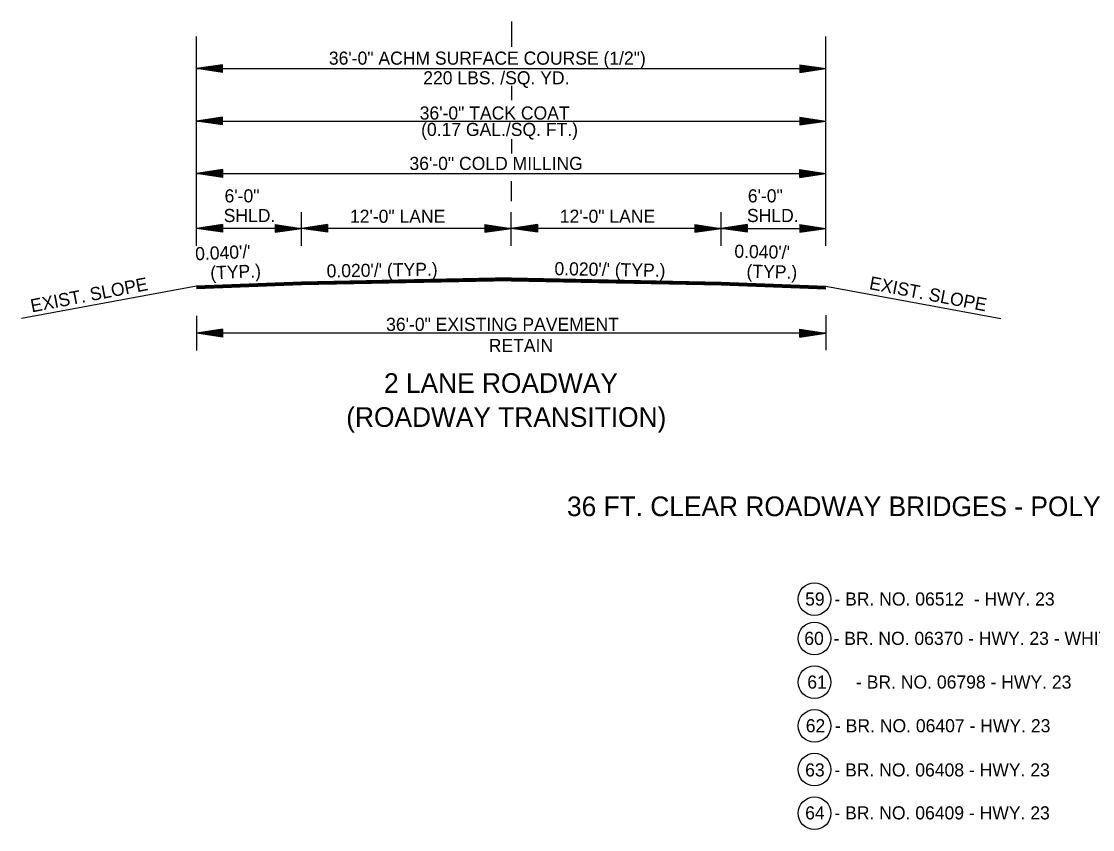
# Model space of a CAD drawing. Extents: x 550980 to 1930787, y -1972975 to 596640.
# Drawn here: x 551028 to 551641, y -1972925 to -1972463 of the extents above; entities that cross this region are included whole.
import ezdxf

# ---------------------------------------------------------------- set-up
doc = ezdxf.new("R2010")
doc.units = 0
doc.layers.add('R_Border', color=7, linetype='Continuous')
doc.layers.add('R_Draft', color=7, linetype='Continuous')

msp = doc.modelspace()

# ---------------------------------------------------------------- linework, layer by layer
at = {"layer": 'R_Border'}
for p, q in [((551308.3, -1972462.9), (551308.3, -1972477.4)), ((551143.09, -1972487.65), (551128.09, -1972489.9)), ((551128.09, -1972489.9), (551488.09, -1972489.9)), ((551143.09, -1972492.15), (551128.09, -1972489.9)), ((551143.09, -1972488.03), (551130.59, -1972489.9)), ((551143.09, -1972491.78), (551130.59, -1972489.9)), ((551143.09, -1972488.41), (551133.17, -1972489.9)), ((551143.09, -1972491.39), (551133.17, -1972489.9)), ((551143.09, -1972488.78), (551135.67, -1972489.9)), ((551143.09, -1972491.02), (551135.67, -1972489.9)), ((551143.09, -1972489.17), (551138.21, -1972489.9)), ((551143.09, -1972490.63), (551138.21, -1972489.9)), ((551143.09, -1972489.55), (551140.72, -1972489.9)), ((551143.09, -1972490.25), (551140.72, -1972489.9)), ((551143.09, -1972492.15), (551143.09, -1972487.65)), ((551473.09, -1972487.65), (551488.09, -1972489.9)), ((551473.09, -1972487.65), (551473.09, -1972492.15)), ((551473.09, -1972488.03), (551485.58, -1972489.9)), ((551473.09, -1972488.41), (551483, -1972489.9)), ((551473.09, -1972488.78), (551480.51, -1972489.9)), ((551473.09, -1972489.17), (551477.96, -1972489.9)), ((551473.09, -1972489.55), (551475.46, -1972489.9)), ((551473.09, -1972492.15), (551488.09, -1972489.9)), ((551473.09, -1972490.64), (551477.96, -1972489.9)), ((551473.09, -1972491.39), (551483, -1972489.9)), ((551473.09, -1972491.78), (551485.58, -1972489.9)), ((551473.09, -1972491.02), (551480.51, -1972489.9)), ((551473.09, -1972490.25), (551475.46, -1972489.9)), ((551308.3, -1972499.84), (551308.3, -1972508.04)), ((551143.09, -1972517.65), (551128.09, -1972519.9)), ((551128.09, -1972519.9), (551488.09, -1972519.9)), ((551143.09, -1972522.15), (551128.09, -1972519.9)), ((551143.09, -1972518.03), (551130.59, -1972519.9)), ((551143.09, -1972521.78), (551130.59, -1972519.9)), ((551143.09, -1972518.41), (551133.17, -1972519.9)), ((551143.09, -1972521.39), (551133.17, -1972519.9)), ((551143.09, -1972518.78), (551135.67, -1972519.9)), ((551143.09, -1972521.02), (551135.67, -1972519.9)), ((551143.09, -1972519.17), (551138.21, -1972519.9)), ((551143.09, -1972520.63), (551138.21, -1972519.9)), ((551143.09, -1972519.55), (551140.72, -1972519.9)), ((551143.09, -1972520.25), (551140.72, -1972519.9)), ((551143.09, -1972522.15), (551143.09, -1972517.65)), ((551473.09, -1972517.65), (551488.09, -1972519.9)), ((551473.09, -1972517.65), (551473.09, -1972522.15)), ((551473.09, -1972518.03), (551485.58, -1972519.9)), ((551473.09, -1972518.41), (551483, -1972519.9)), ((551473.09, -1972518.78), (551480.51, -1972519.9)), ((551473.09, -1972519.17), (551477.96, -1972519.9)), ((551473.09, -1972519.55), (551475.46, -1972519.9)), ((551473.09, -1972522.15), (551488.09, -1972519.9)), ((551473.09, -1972520.64), (551477.96, -1972519.9)), ((551473.09, -1972521.39), (551483, -1972519.9)), ((551473.09, -1972521.78), (551485.58, -1972519.9)), ((551473.09, -1972521.02), (551480.51, -1972519.9)), ((551473.09, -1972520.25), (551475.46, -1972519.9)), ((551308.3, -1972530.36), (551308.3, -1972538.56)), ((551128.09, -1972549.9), (551488.09, -1972549.9))]:
    msp.add_line(p, q, dxfattribs=at)
for centre in [(551481.56, -1972793.43), (551481.56, -1972815.96), (551481.56, -1972840.96), (551481.56, -1972865.96), (551481.56, -1972890.96), (551481.56, -1972915.96)]:
    msp.add_circle(centre, 9.34, dxfattribs=at)
at = {"layer": 'R_Draft'}
for p, q in [((551128.09, -1972591.31), (551128.09, -1972471.5)), ((551488.09, -1972591.31), (551488.09, -1972471.5)), ((551143.09, -1972547.65), (551128.09, -1972549.9)), ((551143.09, -1972552.15), (551128.09, -1972549.9)), ((551143.09, -1972548.03), (551130.59, -1972549.9)), ((551143.09, -1972551.78), (551130.59, -1972549.9)), ((551143.09, -1972548.41), (551133.17, -1972549.9)), ((551143.09, -1972551.39), (551133.17, -1972549.9)), ((551143.09, -1972548.78), (551135.67, -1972549.9)), ((551143.09, -1972551.02), (551135.67, -1972549.9)), ((551143.09, -1972549.17), (551138.21, -1972549.9)), ((551143.09, -1972550.64), (551138.21, -1972549.9)), ((551143.09, -1972549.55), (551140.72, -1972549.9)), ((551143.09, -1972550.25), (551140.72, -1972549.9)), ((551143.09, -1972547.65), (551143.09, -1972552.15)), ((551473.09, -1972547.65), (551488.09, -1972549.9)), ((551473.09, -1972552.15), (551473.09, -1972547.65)), ((551473.09, -1972548.03), (551485.58, -1972549.9)), ((551473.09, -1972548.41), (551483, -1972549.9)), ((551473.09, -1972548.78), (551480.51, -1972549.9)), ((551473.09, -1972549.17), (551477.96, -1972549.9)), ((551473.09, -1972549.55), (551475.46, -1972549.9)), ((551473.09, -1972552.15), (551488.09, -1972549.9)), ((551473.09, -1972550.63), (551477.96, -1972549.9)), ((551473.09, -1972551.39), (551483, -1972549.9)), ((551473.09, -1972551.78), (551485.58, -1972549.9)), ((551473.09, -1972551.02), (551480.51, -1972549.9)), ((551473.09, -1972550.25), (551475.46, -1972549.9)), ((551308.3, -1972565.67), (551308.3, -1972554.22)), ((551188.09, -1972591.31), (551188.09, -1972572.12)), ((551308.09, -1972591.31), (551308.09, -1972572.12)), ((551428.09, -1972591.31), (551428.09, -1972572.12)), ((551143.09, -1972579.06), (551128.09, -1972581.31)), ((551188.09, -1972581.31), (551128.09, -1972581.31)), ((551143.09, -1972583.56), (551128.09, -1972581.31)), ((551143.09, -1972579.43), (551130.59, -1972581.31)), ((551143.09, -1972583.18), (551130.59, -1972581.31)), ((551143.09, -1972579.82), (551133.17, -1972581.31)), ((551143.09, -1972582.8), (551133.17, -1972581.31)), ((551143.09, -1972580.19), (551135.67, -1972581.31)), ((551143.09, -1972582.43), (551135.67, -1972581.31)), ((551143.09, -1972580.58), (551138.21, -1972581.31)), ((551143.09, -1972582.04), (551138.21, -1972581.31)), ((551143.09, -1972580.96), (551140.72, -1972581.31)), ((551143.09, -1972581.66), (551140.72, -1972581.31)), ((551143.09, -1972579.06), (551143.09, -1972583.56)), ((551173.09, -1972579.06), (551188.09, -1972581.31)), ((551173.09, -1972579.06), (551173.09, -1972583.56)), ((551173.09, -1972579.43), (551185.58, -1972581.31)), ((551173.09, -1972579.82), (551183, -1972581.31)), ((551173.09, -1972580.19), (551180.51, -1972581.31)), ((551173.09, -1972580.58), (551177.96, -1972581.31)), ((551173.09, -1972580.96), (551175.46, -1972581.31)), ((551173.09, -1972583.56), (551188.09, -1972581.31)), ((551173.09, -1972582.04), (551177.96, -1972581.31)), ((551173.09, -1972582.8), (551183, -1972581.31)), ((551173.09, -1972583.18), (551185.58, -1972581.31)), ((551173.09, -1972582.43), (551180.51, -1972581.31)), ((551173.09, -1972581.66), (551175.46, -1972581.31)), ((551203.09, -1972579.06), (551188.09, -1972581.31)), ((551308.09, -1972581.31), (551188.09, -1972581.31)), ((551203.09, -1972583.56), (551188.09, -1972581.31)), ((551203.09, -1972579.43), (551190.59, -1972581.31)), ((551203.09, -1972583.18), (551190.59, -1972581.31)), ((551203.09, -1972579.82), (551193.17, -1972581.31)), ((551203.09, -1972582.8), (551193.17, -1972581.31)), ((551203.09, -1972580.19), (551195.67, -1972581.31)), ((551203.09, -1972582.43), (551195.67, -1972581.31)), ((551203.09, -1972580.58), (551198.21, -1972581.31)), ((551203.09, -1972582.04), (551198.21, -1972581.31)), ((551203.09, -1972580.96), (551200.72, -1972581.31)), ((551203.09, -1972581.66), (551200.72, -1972581.31)), ((551203.09, -1972579.06), (551203.09, -1972583.56)), ((551293.09, -1972579.06), (551308.09, -1972581.31)), ((551293.09, -1972579.06), (551293.09, -1972583.56)), ((551293.09, -1972579.43), (551305.58, -1972581.31)), ((551293.09, -1972579.82), (551303, -1972581.31)), ((551293.09, -1972580.19), (551300.51, -1972581.31)), ((551293.09, -1972580.58), (551297.96, -1972581.31)), ((551293.09, -1972580.96), (551295.46, -1972581.31)), ((551293.09, -1972583.56), (551308.09, -1972581.31)), ((551293.09, -1972582.04), (551297.96, -1972581.31)), ((551293.09, -1972582.8), (551303, -1972581.31)), ((551293.09, -1972583.18), (551305.58, -1972581.31)), ((551293.09, -1972582.43), (551300.51, -1972581.31)), ((551293.09, -1972581.66), (551295.46, -1972581.31)), ((551323.09, -1972579.06), (551308.09, -1972581.31)), ((551428.09, -1972581.31), (551308.09, -1972581.31)), ((551323.09, -1972583.56), (551308.09, -1972581.31)), ((551323.09, -1972579.43), (551310.59, -1972581.31)), ((551323.09, -1972583.18), (551310.59, -1972581.31)), ((551323.09, -1972579.82), (551313.17, -1972581.31)), ((551323.09, -1972582.8), (551313.17, -1972581.31)), ((551323.09, -1972580.19), (551315.67, -1972581.31)), ((551323.09, -1972582.43), (551315.67, -1972581.31)), ((551323.09, -1972580.58), (551318.21, -1972581.31)), ((551323.09, -1972582.04), (551318.21, -1972581.31)), ((551323.09, -1972580.96), (551320.72, -1972581.31)), ((551323.09, -1972581.66), (551320.72, -1972581.31)), ((551323.09, -1972579.06), (551323.09, -1972583.56)), ((551413.09, -1972579.06), (551428.09, -1972581.31)), ((551413.09, -1972579.06), (551413.09, -1972583.56)), ((551413.09, -1972579.43), (551425.58, -1972581.31)), ((551413.09, -1972579.82), (551423, -1972581.31)), ((551413.09, -1972580.19), (551420.51, -1972581.31)), ((551413.09, -1972580.58), (551417.96, -1972581.31)), ((551413.09, -1972580.96), (551415.46, -1972581.31)), ((551413.09, -1972583.56), (551428.09, -1972581.31)), ((551413.09, -1972582.04), (551417.96, -1972581.31)), ((551413.09, -1972582.8), (551423, -1972581.31)), ((551413.09, -1972583.18), (551425.58, -1972581.31)), ((551413.09, -1972582.43), (551420.51, -1972581.31)), ((551413.09, -1972581.66), (551415.46, -1972581.31)), ((551443.09, -1972579.06), (551428.09, -1972581.31)), ((551428.09, -1972581.31), (551488.09, -1972581.31)), ((551443.09, -1972583.56), (551428.09, -1972581.31)), ((551443.09, -1972579.43), (551430.59, -1972581.31)), ((551443.09, -1972583.18), (551430.59, -1972581.31)), ((551443.09, -1972579.82), (551433.17, -1972581.31)), ((551443.09, -1972582.8), (551433.17, -1972581.31)), ((551443.09, -1972580.19), (551435.67, -1972581.31)), ((551443.09, -1972582.43), (551435.67, -1972581.31)), ((551443.09, -1972580.58), (551438.21, -1972581.31)), ((551443.09, -1972582.04), (551438.21, -1972581.31)), ((551443.09, -1972580.96), (551440.72, -1972581.31)), ((551443.09, -1972581.66), (551440.72, -1972581.31)), ((551443.09, -1972579.06), (551443.09, -1972583.56)), ((551473.09, -1972579.06), (551488.09, -1972581.31)), ((551473.09, -1972579.06), (551473.09, -1972583.56)), ((551473.09, -1972579.43), (551485.58, -1972581.31)), ((551473.09, -1972579.82), (551483, -1972581.31)), ((551473.09, -1972580.19), (551480.51, -1972581.31)), ((551473.09, -1972580.58), (551477.96, -1972581.31)), ((551473.09, -1972580.96), (551475.46, -1972581.31)), ((551473.09, -1972583.56), (551488.09, -1972581.31)), ((551473.09, -1972582.04), (551477.96, -1972581.31)), ((551473.09, -1972582.8), (551483, -1972581.31)), ((551473.09, -1972583.18), (551485.58, -1972581.31)), ((551473.09, -1972582.43), (551480.51, -1972581.31)), ((551473.09, -1972581.66), (551475.46, -1972581.31)), ((551188.09, -1972612.02), (551128.09, -1972614.42)), ((551188.09, -1972612.32), (551128.09, -1972614.72)), ((551188.09, -1972612.62), (551128.09, -1972615.02)), ((551188.09, -1972612.92), (551128.09, -1972615.32)), ((551188.09, -1972613.22), (551128.09, -1972615.62)), ((551188.09, -1972613.52), (551128.09, -1972615.92)), ((551308.09, -1972609.62), (551188.09, -1972612.02)), ((551308.09, -1972609.92), (551188.09, -1972612.32)), ((551308.09, -1972610.22), (551188.09, -1972612.62)), ((551308.09, -1972610.52), (551188.09, -1972612.92)), ((551308.09, -1972610.82), (551188.09, -1972613.22)), ((551308.09, -1972611.12), (551188.09, -1972613.52)), ((551308.09, -1972611.29), (551188.09, -1972613.69)), ((551308.09, -1972609.62), (551428.09, -1972612.02)), ((551308.09, -1972609.92), (551428.09, -1972612.32)), ((551308.09, -1972610.22), (551428.09, -1972612.62)), ((551308.09, -1972610.52), (551428.09, -1972612.92)), ((551308.09, -1972610.82), (551428.09, -1972613.22)), ((551308.09, -1972611.12), (551428.09, -1972613.52)), ((551308.09, -1972611.29), (551428.09, -1972613.69)), ((551428.09, -1972612.02), (551488.09, -1972614.42)), ((551428.09, -1972612.32), (551488.09, -1972614.72)), ((551428.09, -1972612.62), (551488.09, -1972615.02)), ((551428.09, -1972612.92), (551488.09, -1972615.32)), ((551428.09, -1972613.22), (551488.09, -1972615.62)), ((551428.09, -1972613.52), (551488.09, -1972615.92)), ((551128.09, -1972614.42), (551028.02, -1972632.8)), ((551488.09, -1972614.42), (551588.16, -1972632.8)), ((551128.09, -1972631.28), (551128.09, -1972651.28)), ((551488.09, -1972631.03), (551488.09, -1972651.03)), ((551143.09, -1972639.03), (551128.09, -1972641.28)), ((551143.09, -1972643.53), (551128.09, -1972641.28)), ((551488.09, -1972641.28), (551128.09, -1972641.28)), ((551143.09, -1972639.4), (551130.59, -1972641.28)), ((551143.09, -1972643.15), (551130.59, -1972641.28)), ((551143.09, -1972639.78), (551133.17, -1972641.28)), ((551143.09, -1972642.77), (551133.17, -1972641.28)), ((551143.09, -1972640.16), (551135.67, -1972641.28)), ((551143.09, -1972642.39), (551135.67, -1972641.28)), ((551143.09, -1972640.55), (551138.21, -1972641.28)), ((551143.09, -1972642.01), (551138.21, -1972641.28)), ((551143.09, -1972640.92), (551140.72, -1972641.28)), ((551143.09, -1972641.63), (551140.72, -1972641.28)), ((551143.09, -1972639.03), (551143.09, -1972643.53)), ((551473.09, -1972639.03), (551488.09, -1972641.28)), ((551473.09, -1972643.53), (551473.09, -1972639.03)), ((551473.09, -1972639.4), (551485.58, -1972641.28)), ((551473.09, -1972639.78), (551483, -1972641.28)), ((551473.09, -1972640.16), (551480.51, -1972641.28)), ((551473.09, -1972640.54), (551477.96, -1972641.28)), ((551473.09, -1972640.92), (551475.46, -1972641.28)), ((551473.09, -1972643.53), (551488.09, -1972641.28)), ((551473.09, -1972642), (551477.96, -1972641.28)), ((551473.09, -1972642.77), (551483, -1972641.28)), ((551473.09, -1972643.15), (551485.58, -1972641.28)), ((551473.09, -1972642.39), (551480.51, -1972641.28)), ((551473.09, -1972641.63), (551475.46, -1972641.28))]:
    msp.add_line(p, q, dxfattribs=at)

# ---------------------------------------------------------------- texts
at = {"layer": 'R_Border'}
for s, height, p in [('36\'-0" ACHM SURFACE COURSE (1/2")', 7.5, (551203.83, -1972487.66)), ('220 LBS. /SQ. YD.', 7.5, (551257.81, -1972498.91)), ('36\'-0" TACK COAT', 7.5, (551255.77, -1972519.06)), ('(0.17 GAL./SQ. FT.)', 7.5, (551256.57, -1972528.45)), ('36\'-0" COLD MILLING', 7.5, (551249.92, -1972547.9)), ('(ROADWAY TRANSITION)', 11.25, (551213.77, -1972694.89))]:
    msp.add_text(s, height=height, dxfattribs=at).set_placement(p)
at = {"layer": 'R_Draft'}
for s, height, p in [('6\'-0"', 7.5, (551144.18, -1972566.45)), ('6\'-0"', 7.5, (551443.42, -1972566.45)), ('SHLD.', 7.5, (551143.68, -1972577.7)), ('12\'-0" LANE', 7.5, (551215.9, -1972578.14)), ('12\'-0" LANE', 7.5, (551335.9, -1972578.14)), ('SHLD.', 7.5, (551442.92, -1972577.7)), ('36\'-0" EXISTING PAVEMENT ', 7.5, (551236.58, -1972639.95)), ('RETAIN', 7.5, (551295.28, -1972652.05)), ('2 LANE ROADWAY', 11.25, (551235.36, -1972675.41)), ('36 FT. CLEAR ROADWAY BRIDGES - POLYMER OVERLAY', 11.25, (551340.01, -1972745.96)), ('59  - BR. NO. 06512  - HWY. 23', 7.5, (551476.19, -1972797.1)), ('60  - BR. NO. 06370 - HWY. 23 - WHITE RIVER', 7.5, (551475.71, -1972819.62)), ('61      - BR. NO. 06798 - HWY. 23', 7.5, (551477.42, -1972844.62)), ('62  - BR. NO. 06407 - HWY. 23', 7.5, (551476.54, -1972869.62)), ('63  - BR. NO. 06408 - HWY. 23', 7.5, (551476.2, -1972894.89)), ('64  - BR. NO. 06409 - HWY. 23', 7.5, (551476.2, -1972919.47))]:
    msp.add_text(s, height=height, dxfattribs=at).set_placement(p)
for s, rotation, p in [("  0.040'/'", 2.44797, (551121.97, -1972599.84)), ("0.040'/'", 358.68162, (551435.66, -1972598.07)), ("0.020'/' (TYP.)", 0.97192, (551202.61, -1972609.41)), ("0.020'/' (TYP.)", 359.02808, (551332.79, -1972608.04)), (' (TYP.)', 2.44797, (551133.39, -1972610.62)), ('(TYP.)', 358.68162, (551442.6, -1972609.48)), ('EXIST. SLOPE', 10.88286, (551034, -1972629.42)), ('EXIST. SLOPE', 349.11714, (551512.47, -1972616.01))]:
    msp.add_text(s, height=7.5, rotation=rotation, dxfattribs=at).set_placement(p)

doc.saveas('drawing.dxf')
